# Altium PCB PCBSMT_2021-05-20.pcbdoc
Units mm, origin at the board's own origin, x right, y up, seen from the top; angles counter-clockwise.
Board outline 105.9 x 153.18 mm, 2 copper layers (Top Layer, Bottom Layer); 25 components, 8 nets, 52 pads, 3 vias.
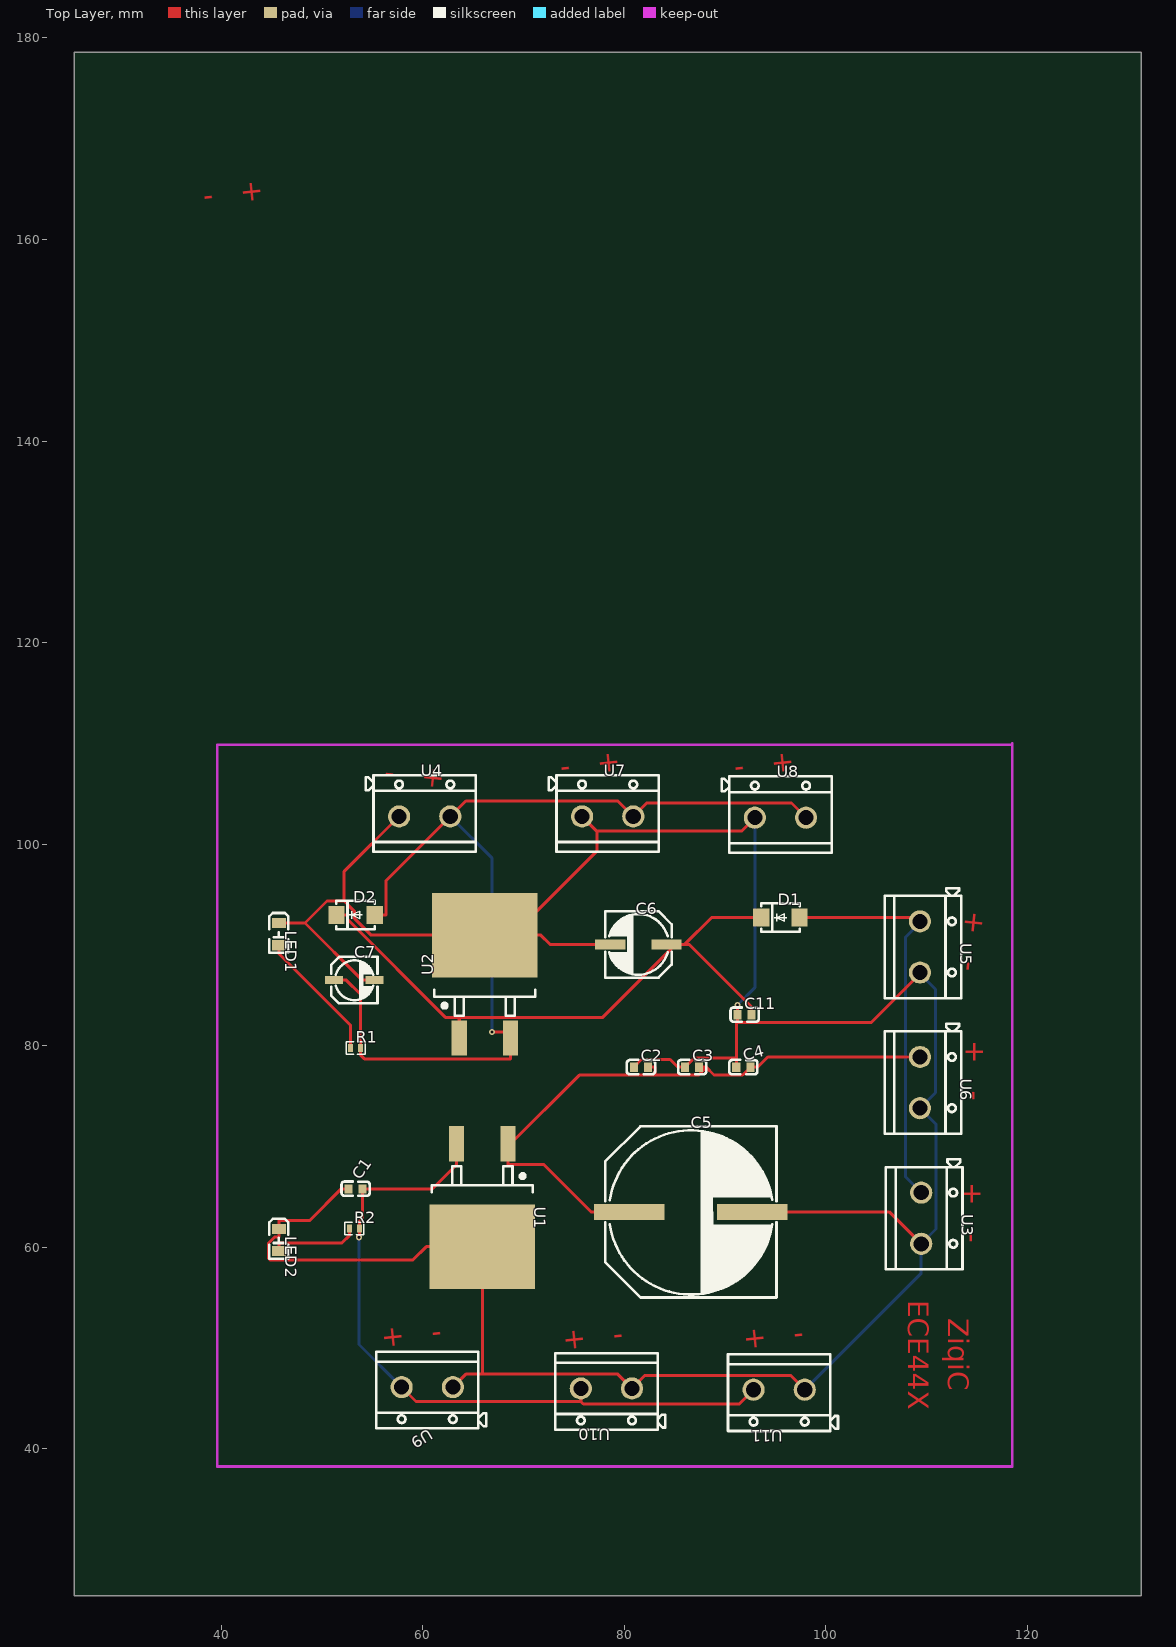
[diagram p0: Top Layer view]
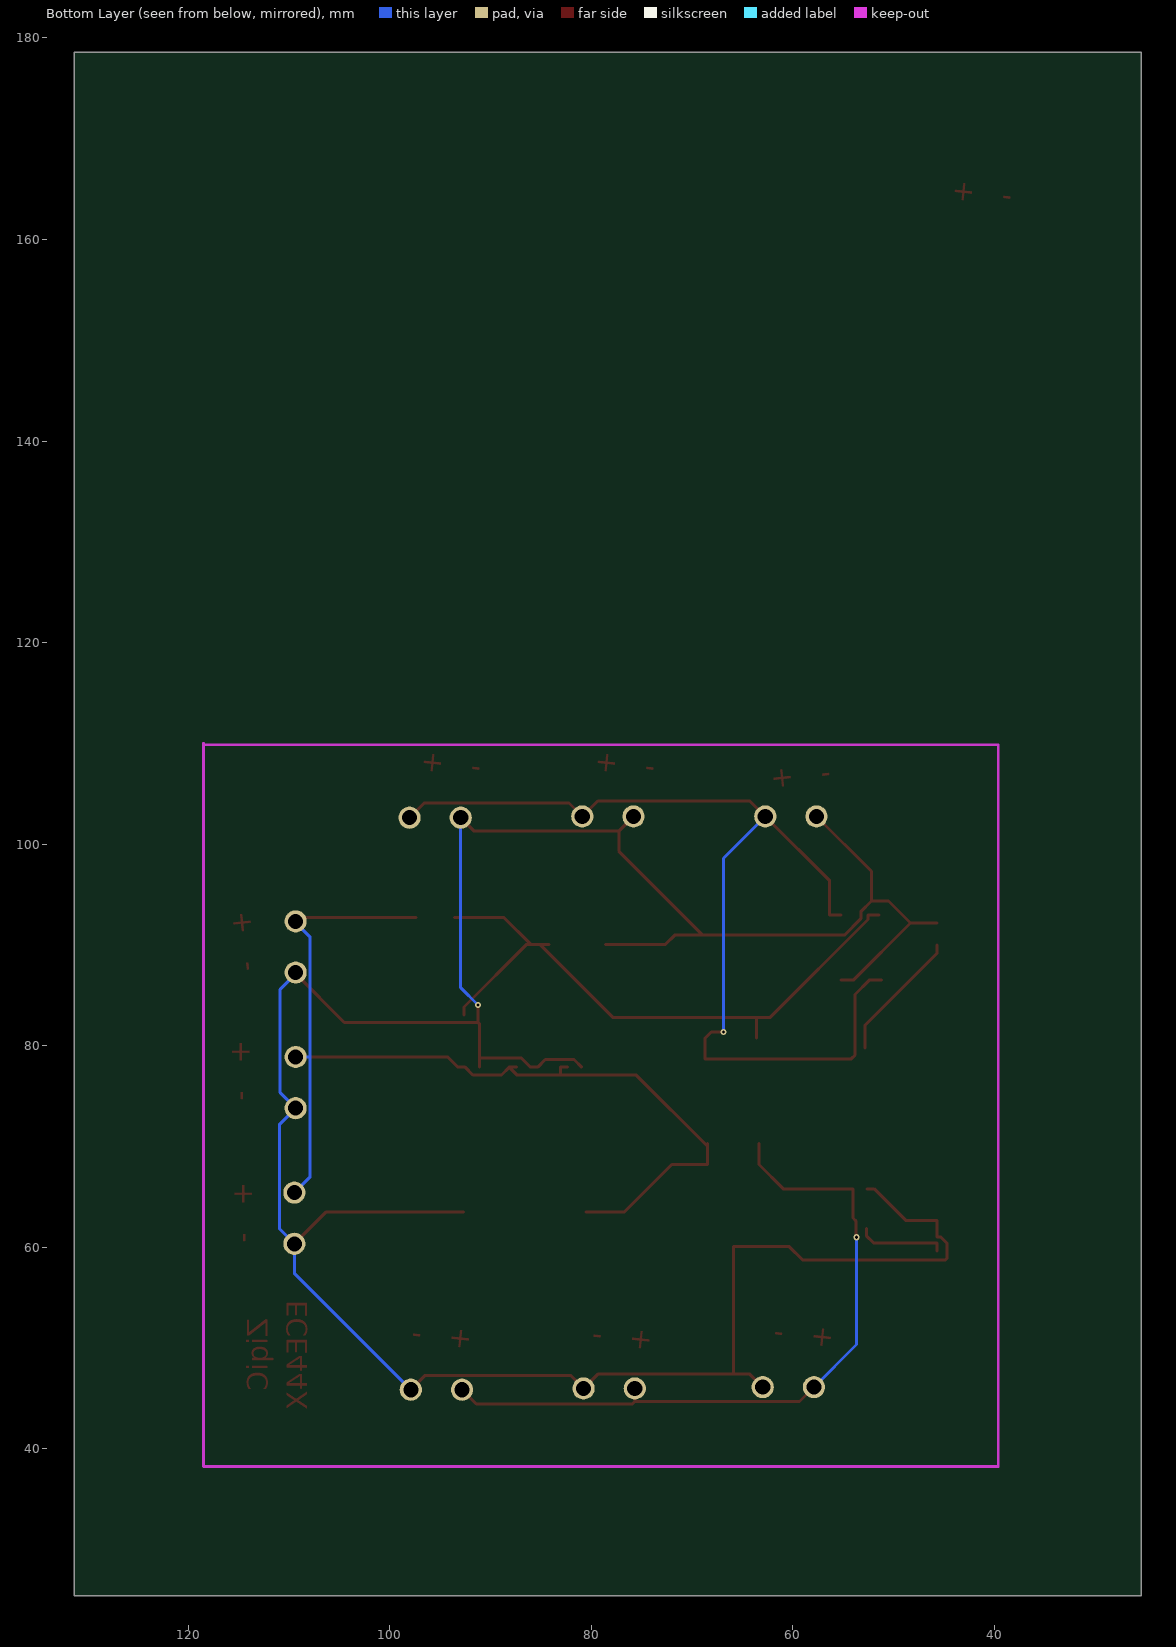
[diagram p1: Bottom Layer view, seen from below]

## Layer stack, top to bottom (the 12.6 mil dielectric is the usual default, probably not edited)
Top Layer: signal copper (thickness not stored)
Dielectric: dielectric 0.32, FR-4, Dk 4.8
Bottom Layer: signal copper (thickness not stored)

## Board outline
131.297,25.4 25.4,25.4 25.4,178.579 131.297,178.579

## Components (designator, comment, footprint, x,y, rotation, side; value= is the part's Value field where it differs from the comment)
C1 "100nF" C0603 53.319,65.786 r0 top
C2 "100nF" C0603 81.64,77.851 r0 top
C3 "100nF" C0603 86.72,77.851 r0 top
C4 "100nF" C0603 91.8,77.851 r0 top
C5 "1000uF" CAP-SMD_BD16.0-L17.0-W17.0-FD 86.593,63.5 r0 top
C6 "100uF" CAP-SMD_BD6.3-L6.6-W6.6-RD 81.386,90.043 r0 top
C7 "100nF" CAP-SMD_BD4.0-L4.3-W4.3-FD 53.192,86.487 r0 top
C11 "100nF" C0603 91.927,83.058 r0 top
D1 "1N4004F" SMAF_L3.5-W2.6-LS4.7-RD 95.483,92.71 r0 top
D2 "1N4004F" SMAF_L3.5-W2.6-LS4.7-RD 53.319,92.964 r0 top
LED1 "17-21SYGC/S530-E3/TR8" LED0805-RD 45.699,91.059 r270 top
LED2 "17-21SYGC/S530-E3/TR8" LED0805-RD 45.699,60.706 r270 top
R1 "1K" R0402 53.319,79.756 r0 top
R2 "1K" R0402 53.192,61.849 r0 top
U1 "L7812CD2T-TR" TO-263-2_L10.0-W9.1-P5.08-LS15.2-TL 65.892,65.151 r270 top
U2 "L7805CD2T-TR" TO-263-2_L10.0-W9.1-P5.08-LS15.2-TL 66.146,85.852 r90 top
U3 "JL301-50002U02" CONN-TH_2P-P2.54_JL301-50002U02 109.453,62.865 r270 top
U4 "JL301-50002U02" CONN-TH_2P-P2.54_JL301-50002U02 60.177,102.743 r0 top
U5 "JL301-50002U02" CONN-TH_2P-P2.54_JL301-50002U02 109.326,89.789 r270 top
U6 "JL301-50002U02" CONN-TH_2P-P2.54_JL301-50002U02 109.326,76.327 r270 top
U7 "JL301-50002U02" CONN-TH_2P-P2.54_JL301-50002U02 78.338,102.743 r0 top
U8 "JL301-50002U02" CONN-TH_2P-P2.54_JL301-50002U02 95.483,102.616 r0 top
U9 "JL301-50002U02" CONN-TH_2P-P2.54_JL301-50002U02 60.431,46.101 r180 top
U10 "JL301-50002U02" CONN-TH_2P-P2.54_JL301-50002U02 78.211,45.974 r180 top
U11 "JL301-50002U02" CONN-TH_2P-P2.54_JL301-50002U02 95.356,45.847 r180 top

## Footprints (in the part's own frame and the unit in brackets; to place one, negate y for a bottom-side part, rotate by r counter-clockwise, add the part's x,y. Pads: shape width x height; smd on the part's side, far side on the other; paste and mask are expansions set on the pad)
C0603 [mm]
  rect 0.8x0.9 smd: 1(-0.7,0) 2(0.7,0)
  silkscreen extent -1.4,-0.7 1.4,0.72
CAP-SMD_BD4.0-L4.3-W4.3-FD [mm]
  rect 1.8x0.8 smd: 1(-2,0) 2(2,0)
  silkscreen extent -2.3,-2.29 2.3,2.31
CAP-SMD_BD6.3-L6.6-W6.6-RD [mm]
  rect 3x1 smd: 1(2.8,0) 2(-2.8,0)
  silkscreen extent -3.3,-3.3 3.3,3.3
CAP-SMD_BD16.0-L17.0-W17.0-FD [mm]
  rect 7x1.6 smd: 1(-6.096,0) 2(6.096,0)
  silkscreen extent -8.51,-8.5 8.5,8.5
CONN-TH_2P-P2.54_JL301-50002U02 [mm]
  round 2.2 hole 1.5: 1(-2.54,0) 2(2.54,0)
  silkscreen extent -5.84,-3.5 5.08,4.1
LED0805-RD [mm]
  rect 1x1.4 smd: 1(-1.1,0) 2(1.1,0)
  silkscreen extent -2.1,-0.95 1.85,0.95
R0402 [mm]
  rect 0.5x0.8 smd: 1(-0.5,0) 2(0.5,0)
  silkscreen extent -0.95,-0.6 0.95,0.6
SMAF_L3.5-W2.6-LS4.7-RD [mm]
  rect 1.6x1.8 smd: 1(-1.9,0) 2(1.9,0)
  silkscreen extent -1.9,-1.4 1.9,1.4
TO-263-2_L10.0-W9.1-P5.08-LS15.2-TL [mm]
  rect 3.504x1.5 smd: 1(-5.106,2.54) 3(-5.106,-2.54)
  rect 8.38x10.49 smd: 4(5.107,0)
  silkscreen extent -2.89,-5 -0.29,5

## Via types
v1: diameter 0.61, hole 0.31, Top Layer to Bottom Layer, 3 vias

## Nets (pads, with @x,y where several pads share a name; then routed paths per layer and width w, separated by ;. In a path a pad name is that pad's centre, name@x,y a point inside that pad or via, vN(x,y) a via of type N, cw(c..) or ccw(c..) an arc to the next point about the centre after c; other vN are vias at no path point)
C1_2: C1.2 R2.2 U1.3 U9.2 U10.2 U11.2 | length 71.5
  Top Layer w0.3: v1(53.657,60.983) 53.693,61.018 R2.2 53.693,62.56 54.02,62.888 54.02,65.786 60.944,65.786 63.352,68.194 U1.3 ; U9.2 59.316,44.676 75.671,44.676 ; U10.2 75.671,44.676 ; U11.2 91.399,44.43 75.915,44.43 75.671,44.676
  Bottom Layer w0.3: v1(53.657,60.983) 53.657,50.335 U9.2
C2_2: C2.2 C3.2 C4.2 C5.1 D1.2 U1.1 U3.1 U5.1 U6.1 | length 105.1
  Top Layer w0.3: U1.1 U1.1@68.432,69.98 ; C5.1 76.685,63.5 71.993,68.194 68.432,68.194 68.432,69.225 U1.1@68.432,69.98 ; C2.2@82.341,77.851 83.052,77.851 83.052,77.064 ; C3.2@87.421,77.851 88.132,77.851 ; D1.2 108.818,92.71 U5.1@109.326,92.202 ; U6.1 94.228,78.867 93.212,77.851 92.501,77.851 91.737,77.089 88.894,77.089 88.132,77.851 ; U1.1@68.432,69.98 75.519,77.064 83.052,77.064 ; 83.052,77.064 87.345,77.064 88.132,77.851
  Bottom Layer w0.3: U6.1 107.889,78.867 ; U5.1@109.326,92.202 107.889,90.764 107.889,78.867 ; U3.1 107.889,66.97 107.889,78.867
C11_2: C6.1 C11.2 D1.1 D2.1 U2.1 | length 63.7
  Top Layer w0.3: D2.1 52.532,92.964 52.532,92.502 62.222,82.809 63.606,82.809 ; U2.1@63.606,80.744 63.606,82.809 ; C6.1 C6.1@85.092,90.043 ; C11.2@92.628,83.058 92.628,83.82 86.405,90.043 85.999,90.043 ; D1.1 88.666,92.71 85.999,90.043 ; 63.606,82.809 77.861,82.809 C6.1@85.092,90.043 ; C6.1@85.092,90.043 85.999,90.043
GND: C1.1 C2.1 C3.1 C4.1 C5.2 C6.2 C7.2 C11.1 LED1.1 LED2.1 U1.4 U2.4 U3.2 U4.1 U5.2 U6.2 U7.1 U8.1 U9.1 U10.1 U11.1 | length 295.7
  Top Layer w0.3: LED1.1 48.308,92.159 ; C1.1 51.907,65.786 48.74,62.619 45.699,62.619 45.699,62.067 LED2.1 45.699,60.993 45.293,60.993 44.686,60.386 44.686,58.882 44.831,58.737 59.027,58.737 60.335,60.043 65.892,60.043 65.892,47.386 ; C7.2 53.98,86.487 48.308,92.159 ; U4.1 52.184,97.29 52.184,94.341 ; U9.1 64.256,47.386 65.892,47.386 ; U7.1 77.259,101.282 ; C6.2@78.587,90.043 72.621,90.043 71.704,90.957 U2.4@68.925,90.957 ; C2.1 81.704,78.613 84.546,78.613 85.308,77.851 C3.1 86.928,78.76 91.099,78.76 ; C4.1 91.099,78.76 ; v1(91.226,84.033) C11.1 91.226,82.296 ; C5.2 106.278,63.5 U3.2 ; U8.1 91.61,101.282 77.259,101.282 ; U11.1 96.474,47.269 82.049,47.269 U10.1 79.339,47.386 65.892,47.386 ; U5.2@109.326,87.122 104.5,82.296 91.226,82.296 ; 48.308,92.159 50.49,94.341 52.184,94.341 ; 52.184,94.341 53.233,93.292 53.233,92.591 54.866,90.957 U2.4 U2.4@68.925,90.957 ; U2.4@68.925,90.957 77.259,99.291 77.259,101.282 ; 91.099,78.76 91.099,82.169 91.226,82.296
  Bottom Layer w0.3: v1(91.226,84.033) 92.943,85.748 U8.1 ; U11.1 109.453,57.404 U3.2 110.914,61.785 110.914,72.2 U6.2 110.868,75.329 110.868,85.58 U5.2@109.326,87.122
LED1_2: LED1.2 R1.1 | length 13.2
  Top Layer w0.3: LED1.2 45.699,89.146 52.819,82.027 R1.1
R2_1: LED2.2 R2.1 | length 8.8
  Top Layer w0.3: LED2.2 45.699,60.419 51.976,60.419 52.692,61.135 R2.1
S$68: 
U2_3: C7.1 D2.2 R1.2 U2.3 U4.2 U7.2 U8.2 | length 102.8
  Top Layer w0.3: C7.1@51.193,86.487 52.405,86.487 53.82,85.072 R1.2 53.82,79.042 54.183,78.682 68.686,78.682 68.686,80.744 68.077,81.354 v1(66.873,81.354) ; D2.2 56.332,92.964 56.332,96.357 U4.2 64.259,104.282 79.339,104.282 U7.2 82.204,104.069 96.57,104.069 U8.2
  Bottom Layer w0.3: U4.2 66.873,98.588 v1(66.873,81.354)

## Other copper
Top Layer:
  text "-   +" at 38.312,163.328 h2.03 r6
  text "-   +" at 73.745,106.686 h2.03 r6
  text "-   +" at 91.017,106.686 h2.03 r6
  text "-   +" at 56.134,106.178 h2.03 r354
  text "+   -" at 113.904,93.451 h2.03 r264
  text "+   -" at 113.898,80.518 h2.03 r270
  text "+   -" at 113.644,66.421 h2.03 r270
  text "ECE44X" at 108.183,54.737 h2.03 r270
  text "ZiqiC" at 112.12,52.959 h2.03 r270
  text "+   -" at 55.965,50.044 h2.03 r6
  text "+   -" at 91.906,49.917 h2.03 r6
  text "+   -" at 73.999,49.79 h2.03 r6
